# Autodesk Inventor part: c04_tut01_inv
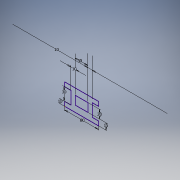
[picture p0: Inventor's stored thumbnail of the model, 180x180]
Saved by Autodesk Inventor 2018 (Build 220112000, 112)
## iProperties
Created: 2017-04
Part Number: c04_tut01_inv
Material: Generic
Document SubType Name: Modeling
Designer: CADCIM 00
Density: 1 g/cm^3
Appearance: Default
Author: CADCIM 00
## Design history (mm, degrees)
sketch "Sketch1"
  geometry: 1 further point
sketch "Sketch2"
  geometry: L1 (0, 0)-(0, 10); L2 (0, 10)-(-15, 10); L3 (-15, 10)-(-15, 40); L4 (-15, 40)-(0, 40); L5 (0, 40)-(0, 50); L6 (0, 50)-(-80, 50); L7 (-80, 50)-(-80, 40); L8 (-80, 40)-(-65, 40); L9 (-65, 40)-(-65, 10); L10 (-65, 10)-(-80, 10); L11 (-80, 0)-(0, 0); L12 (-80, 10)-(-80, 0); L13 (-25, 35)-(-55, 35); L14 (-55, 35)-(-55, 15); L15 (-55, 15)-(-25, 15); L16 (-25, 15)-(-25, 35)
  constraints: 32 end point, 8 perpendicular, 8 point on line, 3 parallel, 2 collinear, 1 horizontal, 1 vertical
  dimensions: "d0" = 80 distance of L11.start L1.start; "d1" = 10 distance of L1.start L1.end; "d2" = 30 distance of L2.end L3.end; "d3" = 10 distance between parallel lines of L16 L3; "d4" = 10 distance between parallel lines of L9 L14; "d5" = 15 distance between parallel lines of L15 L11; "d6" = 20 distance of L13.end L14.end; "d7" = 30 distance of L13.start L13.end
